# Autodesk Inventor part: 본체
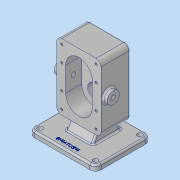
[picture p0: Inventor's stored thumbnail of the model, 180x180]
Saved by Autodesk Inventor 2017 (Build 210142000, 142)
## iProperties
Part Number: 본체
Material: 알루미늄 6061
Document SubType Name: Modeling
Designer: MRC
Density: 2.7 g/cm^3
Appearance: 알루미늄 - 평지
Mass: 1472.54 g
Surface Area: 818.394 cm^2
Volume: 545.387 cm^3
Author: MRC
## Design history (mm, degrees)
sketch "스케치1"
  geometry: L1 (-40, -60)-(40, -60); L2 (40, -60)-(40, 60); L3 (40, 60)-(-40, 60); L4 (-40, 60)-(-40, -60); L5 (-40, -60)-(40, 60); L6 (40, -60)-(-40, 60); 1 further point
  constraints: 12 end point, 2 midpoint, 2 parallel, 1 horizontal, 1 perpendicular
  dimensions: "d0" = 80 distance of L3.end L2.end; "d1" = 120 distance of L2.end L1.end
extrude "돌출1" new body sketch "스케치1" distance "d2" = 14; taper "d4" = 0 deg; dims "d3" = 39, "d5" = 0
sketch "스케치2"
  geometry: L1 (0, 22)-(0, -22); L2 (24, 22)-(24, -22); L3 (-24, -22)-(-24, 22); A1 r 24 centre (0, 22) between (24, 22) and (-24, 22); A2 r 24 centre (0, -22) between (-24, -22) and (24, -22); 2 further points
  constraints: 8 end point, 4 point on circle, 4 tangent, 2 centre point, 1 coincident, 1 midpoint, 1 parallel, 1 vertical
  dimensions: "d6" = 44 distance of L1.end L1.start; "d7" = 24 radius of A1
extrude "돌출2" cut sketch "스케치2" distance "d8" = 29; taper "d9" = 0 deg
sketch "스케치3"
  geometry: C1 r 12.5 at (0, -22); C2 r 12.5 at (0, 22); 3 further points
  constraints: 2 centre point, 2 coincident
  dimensions: "d10" = 25 diameter of C1; "d11" = 25 diameter of C2
extrude "돌출3" cut sketch "스케치3" distance "d12" = 15; taper "d13" = 0 deg
sketch "스케치4"
  geometry: C1 r 19 at (0, 22); A1 r 24 centre (0, 22) between (24, 22) and (-24, 22) reference; 1 further point
  constraints: 1 centre point, 1 coincident
  dimensions: "d14" = 38 diameter of C1
extrude "돌출4" join sketch "스케치4" distance "d15" = 17; taper "d16" = 0 deg
sketch "스케치5"
  geometry: L1 (9.5, -30)-(34.5, -30) reference; L2 (22, -30)-(22, -56); L3 (3, -56)-(41, -56) reference; L4 (36.404, -56)-(36, -55.3); L5 (36, -55.3)-(36, -48.7); L6 (36, -48.7)-(30.5, -48.7); L7 (30.5, -48.7)-(30.5, -30); L8 (30.5, -30)-(22, -30); L9 (36.404, -56)-(22, -56); 1 further point
  constraints: 14 end point, 2 collinear, 2 midpoint, 2 perpendicular, 2 point on line, 1 vertical
  dimensions: "d17" = 28 diameter of L5 L2; "d18" = 17 diameter of L7 L2; "d19" = 7.3 distance from line of L2.end L6; "d20" = 30 deg angle of L5 L4; "d21" = 0.7 vertical distance of L4.start L4.end
revolve "회전1" sketch "스케치5" stored, may be unused: angle "d22" = 90 deg
fillet "모깎기1" dims "d23" = 0.5
sketch "스케치6"
  geometry: L1 (-90, -56)-(-90, 44); L2 (-90, 44)-(-80, 44); L3 (-80, 44)-(-80, -56); L4 (-80, -56)-(-90, -56); 2 further points
  constraints: 8 end point, 2 perpendicular, 1 horizontal, 1 horizontal alignment, 1 vertical
  dimensions: "d24" = 100 distance of L1.start L1.end; "d25" = 90 distance from line of point (0, 0) L1; "d26" = 10 distance of L1.end L2.end
extrude "돌출5" join sketch "스케치6" stored distance "d27" = 120; taper "d28" = 0 deg
fillet "모깎기2" dims "d29" = 10
sketch "스케치7"
  geometry: C1 r 4.5 at (0, 90); C2 r 4.5 at (0, 10); C3 r 4.5 at (100, 10); C4 r 4.5 at (100, 90); 5 further points
  constraints: 4 centre point, 4 coincident
  dimensions: "d30" = 9 diameter of C1; "d31" = 9 diameter of C2; "d32" = 9 diameter of C3; "d33" = 9 diameter of C4
extrude "돌출6" cut sketch "스케치7" stored distance "d34" = 120; taper "d35" = 0 deg
sketch "스케치9"
  geometry: L1 (-60, 2.453)-(-80, 14); L2 (-80, 14)-(-80, -39); L3 (-80, -39)-(-60, -27.453); L4 (-60, -27.453)-(-60, 2.453); L5 (-60, 14)-(-60, -39) reference; L6 (-80, 34)-(-80, -46) reference; L7 (-80, -56)-(-90, -56) reference; 1 further point
  constraints: 8 end point, 2 point on line, 1 parallel, 1 vertical
  dimensions: "d39" = 60 deg angle of L2 L3; "d40" = 60 deg angle of L2 L1; "d41" = 17 distance from line of L7 L2.end; "d42" = 53 distance of L1.end L2.end
extrude "돌출7" join sketch "스케치9" stored distance "d43" = 48; taper "d44" = 0 deg
sketch "스케치10"
  geometry: C1 r 11 at (14, 60); 1 further point
  constraints: 1 centre point, 1 coincident
  dimensions: "d45" = 22 diameter of C1
extrude "돌출8" join sketch "스케치10" distance "d46" = 8; taper "d47" = 0 deg
hole "구멍1" diameter "d50" = 8.376; stored, may be unused: countersink angle "d54" = 90 deg, drill point angle "d56" = 118 deg; dims "d48" = 10, "d49" = 10, "d51" = 96, "d52" = 10, "d53" = 7.3, "d55" = 27.3
fillet "모깎기3" dims "d57" = 9
sketch "스케치11"
  geometry: 7 further points
  constraints: 3 vertical alignment, 2 coincident
  dimensions: "d58" = 29 distance of point (31, 51) point (31, 22); "d59" = 44 distance of point (31, -22) point (31, 22)
hole "구멍2" sketch "스케치11" at (31, 51), (31, -51), (31, 22), (31, -22) diameter "d60" = 4.134; stored, may be unused: countersink angle "d64" = 90 deg, drill point angle "d66" = 118 deg; dims "d61" = 10, "d62" = 10, "d63" = 7.3, "d65" = 12
sketch "스케치12" dims "d0" = 80, "d1" = 120
  geometry: 4 further points
  constraints: 1 other
  dimensions: "d67" = 10 vertical distance of point (0, 0) point (50, 10); "d68" = 60 distance of point (-10, 10) point (50, 10)
feature "엠보싱1" sketch "스케치12" dims "d0" = 80, "d1" = 120, "d69" = 0.5, "d70" = 0
fillet "모깎기4" dims "d71" = 3
fillet "모깎기5" dims "d72" = 3
chamfer "모따기1" distance "d73" = 1; stored, may be unused: second distance "d74" = 2, angle "d75" = 45 deg
node "솔리드1"
mirror "미러1"
mirror "미러2"
